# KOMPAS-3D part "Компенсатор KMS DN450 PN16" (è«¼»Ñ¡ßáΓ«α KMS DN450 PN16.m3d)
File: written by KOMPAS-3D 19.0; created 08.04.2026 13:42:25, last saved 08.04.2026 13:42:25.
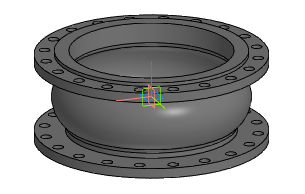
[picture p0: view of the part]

Document properties: Автор: Энергия; Полное имя файла: Z:\3.Личные\kachalov\3d для проектировщиков\7.1 Компенсатор\stp_Компенсатор KSM\Компенсатор KMS DN450 PN16.m3d

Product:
- Part/product: Компенсатор KMS DN450 PN16

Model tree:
1. Операция без истории:1  (labels: Компенсатор KMS DN450 PN16)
